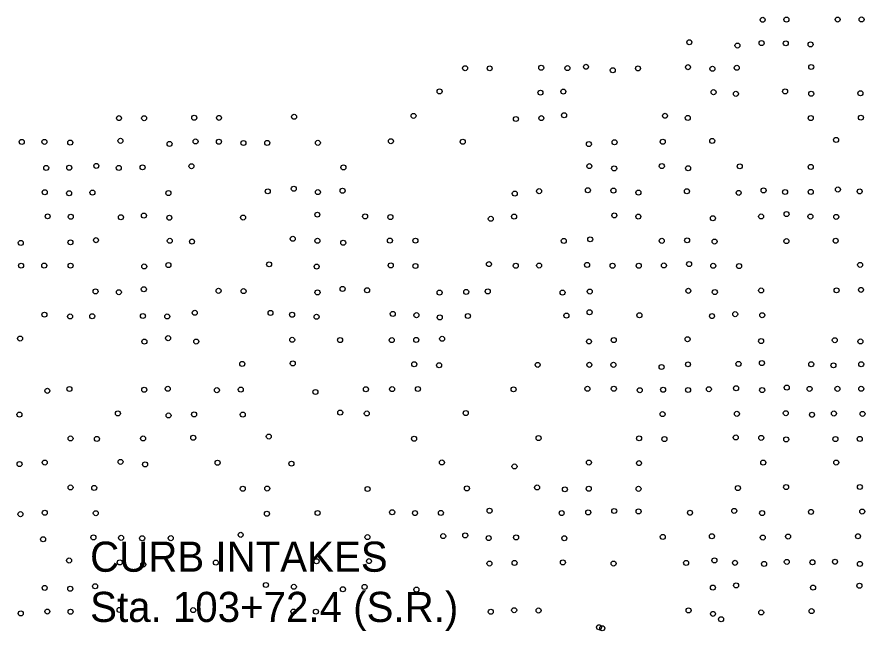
# Model space of a CAD drawing. Extents: x 20503438 to 20508873, y 7964251 to 7984667.
# Drawn here: x 20505367.3 to 20505705.3, y 7970608.3 to 7970852.8 of the extents above; entities that cross this region are included whole.
import ezdxf

# ---------------------------------------------------------------- set-up
doc = ezdxf.new("R2010")
doc.units = 0
for name, color, linetype in [('SurPointsNonDTM', 7, 'Continuous'), ('SurSurveyPoints', 7, 'Continuous'), ('SurTxtDrainage', 7, 'Continuous')]:
    doc.layers.add(name, color=color, linetype=linetype)

msp = doc.modelspace()

# ---------------------------------------------------------------- linework, layer by layer
at = {"layer": 'SurPointsNonDTM'}
for centre in [(20505647.88, 7970612.96), (20505599.24, 7970609.78), (20505600.55, 7970609.39)]:
    msp.add_circle(centre, 1, dxfattribs=at)
at = {"layer": 'SurSurveyPoints'}
for centre in [(20505664.48, 7970851.72), (20505673.94, 7970851.79), (20505694.36, 7970851.81), (20505703.91, 7970851.84), (20505635.24, 7970842.78), (20505654.43, 7970841.47), (20505664.04, 7970842.45), (20505673.69, 7970842.34), (20505683.55, 7970841.93), (20505545.86, 7970832.44), (20505555.68, 7970832.38), (20505576.22, 7970832.63), (20505586.64, 7970832.47), (20505594.06, 7970833), (20505604.74, 7970831.63), (20505614.79, 7970832.36), (20505634.71, 7970832.85), (20505644.43, 7970832.19), (20505654.15, 7970832.6), (20505683.81, 7970832.92), (20505535.72, 7970823.19), (20505575.92, 7970822.69), (20505585.04, 7970823.13), (20505644.91, 7970822.89), (20505653.81, 7970822.23), (20505673.42, 7970823.19), (20505683.81, 7970822.28), (20505703.41, 7970822.46), (20505525.33, 7970813.46), (20505585.34, 7970813.69), (20505625.55, 7970813.48), (20505407.96, 7970812.56), (20505417.98, 7970812.53), (20505437.96, 7970812.71), (20505447.81, 7970812.65), (20505477.71, 7970813.08), (20505566.13, 7970812.2), (20505576.27, 7970812.55), (20505634.64, 7970812.64), (20505683.62, 7970812.58), (20505703.63, 7970812.74), (20505408.53, 7970803.51), (20505516.34, 7970803.36), (20505644.36, 7970803.48), (20505693.72, 7970803.86), (20505369.19, 7970803.08), (20505378.22, 7970803.09), (20505388.55, 7970802.81), (20505428.09, 7970802.26), (20505438.48, 7970803.25), (20505447.78, 7970803.17), (20505457.53, 7970802.64), (20505467.06, 7970802.67), (20505487.21, 7970802.71), (20505544.94, 7970803.14), (20505595.2, 7970802.21), (20505605.44, 7970802.94), (20505624.66, 7970803.14), (20505398.92, 7970793.5), (20505436.84, 7970793.41), (20505595.4, 7970793.44), (20505624.29, 7970793.46), (20505655.33, 7970793.35), (20505378.95, 7970792.71), (20505388.14, 7970792.79), (20505407.88, 7970792.7), (20505417.37, 7970792.96), (20505497.4, 7970792.93), (20505605.29, 7970792.53), (20505634.77, 7970792.59), (20505683.63, 7970793.1), (20505467.23, 7970783.39), (20505477.61, 7970784.42), (20505487.23, 7970783.08), (20505497.07, 7970783.63), (20505575.35, 7970783.46), (20505594.82, 7970783.81), (20505604.98, 7970783.7), (20505634.3, 7970783.42), (20505664.86, 7970783.77), (20505673.41, 7970783.13), (20505683.63, 7970783.17), (20505694.48, 7970784.13), (20505703.13, 7970783.37), (20505378.35, 7970783.01), (20505388.08, 7970782.64), (20505397.39, 7970782.9), (20505427.63, 7970782.7), (20505565.7, 7970782.48), (20505614.94, 7970782.89), (20505654.91, 7970782.78), (20505379.52, 7970773.44), (20505388.75, 7970773.29), (20505408.71, 7970773.08), (20505417.9, 7970773.73), (20505428.02, 7970772.88), (20505457.4, 7970772.96), (20505487, 7970774.11), (20505506.04, 7970773.43), (20505516.11, 7970773.15), (20505565.41, 7970773.35), (20505605.35, 7970773.82), (20505614.92, 7970773.35), (20505663.86, 7970773.39), (20505673.98, 7970774.34), (20505683.5, 7970773.36), (20505693.8, 7970773.22), (20505556.13, 7970772.45), (20505644.63, 7970772.66), (20505368.82, 7970762.86), (20505388.61, 7970763.09), (20505398.79, 7970763.95), (20505428.2, 7970763.7), (20505437.05, 7970763.36), (20505477.2, 7970764.49), (20505487.01, 7970763.69), (20505497.3, 7970762.94), (20505515.93, 7970763.78), (20505526.08, 7970763.75), (20505585.21, 7970763.66), (20505595.74, 7970764.28), (20505624.25, 7970763.68), (20505634.37, 7970763.88), (20505645.33, 7970763.4), (20505673.92, 7970763.56), (20505693.57, 7970763.74), (20505368.92, 7970753.79), (20505378.18, 7970753.82), (20505388.67, 7970753.79), (20505418.03, 7970753.48), (20505427.65, 7970754.05), (20505467.78, 7970754.33), (20505486.73, 7970753.43), (20505516.26, 7970753.9), (20505526.09, 7970753.66), (20505555.4, 7970754.41), (20505566.08, 7970753.77), (20505575.38, 7970753.84), (20505594.5, 7970754.08), (20505604.65, 7970753.76), (20505615.07, 7970753.77), (20505625.11, 7970753.88), (20505635.17, 7970754.43), (20505644.79, 7970753.74), (20505655.07, 7970753.62), (20505703.31, 7970754.12), (20505398.61, 7970743.53), (20505407.91, 7970743.23), (20505417.85, 7970744.41), (20505447.65, 7970743.77), (20505457.62, 7970743.65), (20505487.06, 7970743.16), (20505497.07, 7970744.52), (20505506.81, 7970743.99), (20505535.72, 7970743.08), (20505546.33, 7970743.33), (20505554.89, 7970743.56), (20505584.72, 7970743.08), (20505595.57, 7970743.49), (20505634.85, 7970743.77), (20505645.41, 7970743.29), (20505663.87, 7970743.92), (20505693.94, 7970743.97), (20505703.66, 7970744.16), (20505378.21, 7970734.28), (20505388.46, 7970733.57), (20505397.28, 7970733.65), (20505417.51, 7970733.74), (20505427.19, 7970733.57), (20505438.12, 7970735.03), (20505468.34, 7970734.95), (20505476.93, 7970734.27), (20505486.7, 7970733.42), (20505517.07, 7970734.57), (20505526.48, 7970734.08), (20505535.77, 7970733.19), (20505547, 7970733.74), (20505586.27, 7970733.91), (20505595.49, 7970735.23), (20505615.33, 7970734.05), (20505644.28, 7970733.71), (20505653.53, 7970734.48), (20505664.32, 7970734.07), (20505368.52, 7970724.77), (20505418.06, 7970723.55), (20505427.51, 7970724.92), (20505438.75, 7970723.57), (20505476.98, 7970724.26), (20505496.06, 7970724.18), (20505516.65, 7970724.13), (20505526.44, 7970724.22), (20505536.73, 7970724.66), (20505595.27, 7970723.61), (20505605.12, 7970724.15), (20505634.57, 7970724.51), (20505663.87, 7970723.76), (20505693.22, 7970724.11), (20505703.43, 7970723.6), (20505457.08, 7970714.67), (20505477.21, 7970714.87), (20505525.64, 7970714.54), (20505535.54, 7970714.12), (20505574.81, 7970714.28), (20505595.4, 7970714.3), (20505604.97, 7970714.3), (20505624.19, 7970713.43), (20505634.71, 7970714.5), (20505654.84, 7970714.65), (20505664.17, 7970715.01), (20505683.81, 7970714.52), (20505692.69, 7970714.1), (20505703.74, 7970714.51), (20505379.4, 7970703.94), (20505388.19, 7970704.68), (20505418.03, 7970704.38), (20505427.36, 7970704.76), (20505447, 7970704.21), (20505456.49, 7970704.42), (20505486.22, 7970703.48), (20505506.36, 7970704.58), (20505516.78, 7970704.62), (20505527.1, 7970704.68), (20505565.22, 7970704.54), (20505594.64, 7970704.76), (20505605.16, 7970704.79), (20505615.47, 7970704.2), (20505624.8, 7970704.4), (20505634.74, 7970704.28), (20505643.03, 7970704.6), (20505653.86, 7970704.96), (20505664.27, 7970704.24), (20505674.06, 7970705.24), (20505683.16, 7970704.72), (20505694.24, 7970704.74), (20505703.78, 7970704.76), (20505496.11, 7970695.27), (20505368.29, 7970694.48), (20505407.51, 7970694.96), (20505427.69, 7970694.14), (20505437.87, 7970694.55), (20505457.3, 7970694.49), (20505506.71, 7970694.93), (20505546.15, 7970695.09), (20505624.61, 7970694.66), (20505654.21, 7970694.78), (20505673.7, 7970695.03), (20505684.14, 7970694.43), (20505692.88, 7970694.92), (20505704.27, 7970694.77), (20505437.55, 7970685.28), (20505467.65, 7970685.74), (20505575.17, 7970685.13), (20505615.21, 7970685.03), (20505653.74, 7970685.37), (20505663.93, 7970685.21), (20505388.64, 7970684.97), (20505399.15, 7970684.79), (20505417.55, 7970684.98), (20505525.54, 7970684.87), (20505625.32, 7970684.74), (20505673.85, 7970684.6), (20505693.45, 7970684.74), (20505703.16, 7970684.77), (20505378.36, 7970675.38), (20505408.57, 7970675.66), (20505447.25, 7970675.3), (20505476.66, 7970674.93), (20505536.65, 7970675.42), (20505595.22, 7970675.39), (20505615.18, 7970675.15), (20505664.71, 7970675.37), (20505693.81, 7970675.39), (20505368.32, 7970674.77), (20505418.34, 7970674.66), (20505565.57, 7970673.83), (20505388.64, 7970665.45), (20505398.07, 7970665.28), (20505457.3, 7970664.95), (20505467.06, 7970665.04), (20505507.04, 7970664.84), (20505546.6, 7970665.09), (20505574.56, 7970665.46), (20505595.17, 7970664.95), (20505615.01, 7970664.91), (20505654.62, 7970665.23), (20505673.82, 7970665.63), (20505703.21, 7970665.65), (20505585.65, 7970664.71), (20505368.68, 7970654.82), (20505378.39, 7970655.41), (20505398.7, 7970655.2), (20505466.9, 7970655), (20505487.12, 7970655.29), (20505516.82, 7970655.57), (20505525.91, 7970655.25), (20505536.22, 7970655.3), (20505555.65, 7970656.18), (20505584.37, 7970655.28), (20505594.98, 7970655.52), (20505605.3, 7970656.09), (20505615.02, 7970655.92), (20505635.51, 7970655.39), (20505653.15, 7970656.14), (20505664.26, 7970655.27), (20505683.73, 7970655.7), (20505704.17, 7970655.87), (20505377.72, 7970644.82), (20505397.75, 7970645.56), (20505408.79, 7970645.4), (20505417.19, 7970645.24), (20505428.56, 7970645.27), (20505456.45, 7970646.59), (20505506.98, 7970645.68), (20505537.16, 7970646.08), (20505545.93, 7970646.38), (20505555.28, 7970645.3), (20505566.2, 7970645.57), (20505585.43, 7970645.21), (20505624.68, 7970645.77), (20505644.25, 7970646.02), (20505664.5, 7970645.51), (20505674.59, 7970645.91), (20505702.46, 7970646.03), (20505388.07, 7970636.37), (20505408.24, 7970635.63), (20505417.61, 7970634.77), (20505446.56, 7970635.55), (20505486.69, 7970636.08), (20505507.59, 7970636.12), (20505555.59, 7970635.17), (20505565.58, 7970635.39), (20505584.85, 7970635.62), (20505605.05, 7970635.17), (20505633.97, 7970635.4), (20505645.25, 7970636.41), (20505653.45, 7970635.44), (20505665.04, 7970635.01), (20505674.09, 7970635.83), (20505684.32, 7970635.65), (20505693.3, 7970635.87), (20505703.23, 7970635.01), (20505378.34, 7970625.46), (20505388.55, 7970625.13), (20505398.44, 7970626.11), (20505466.51, 7970626.62), (20505477.65, 7970625.89), (20505497.21, 7970624.9), (20505505.84, 7970625.86), (20505526.46, 7970624.78), (20505644.63, 7970625.56), (20505653.89, 7970626.47), (20505684.54, 7970625.57), (20505703.01, 7970626.31), (20505368.8, 7970615.3), (20505379.4, 7970616.04), (20505388.65, 7970615.96), (20505408.2, 7970616.67), (20505437.54, 7970616.6), (20505477.5, 7970616.02), (20505486.43, 7970616), (20505556.13, 7970615.95), (20505565.44, 7970616.57), (20505575.17, 7970616.46), (20505634.94, 7970616.51), (20505644.68, 7970615.12), (20505663.88, 7970615.67), (20505683.96, 7970616.2)]:
    msp.add_circle(centre, 1, dxfattribs=at)

# ---------------------------------------------------------------- texts
at = {"layer": 'SurTxtDrainage'}
for s, p in [('CURB INTAKES', (20505396.44, 7970631.89)), ('Sta. 103+72.4 (S.R.)', (20505396.44, 7970611.89))]:
    msp.add_text(s, height=12, dxfattribs=at).set_placement(p)

doc.saveas('drawing.dxf')
